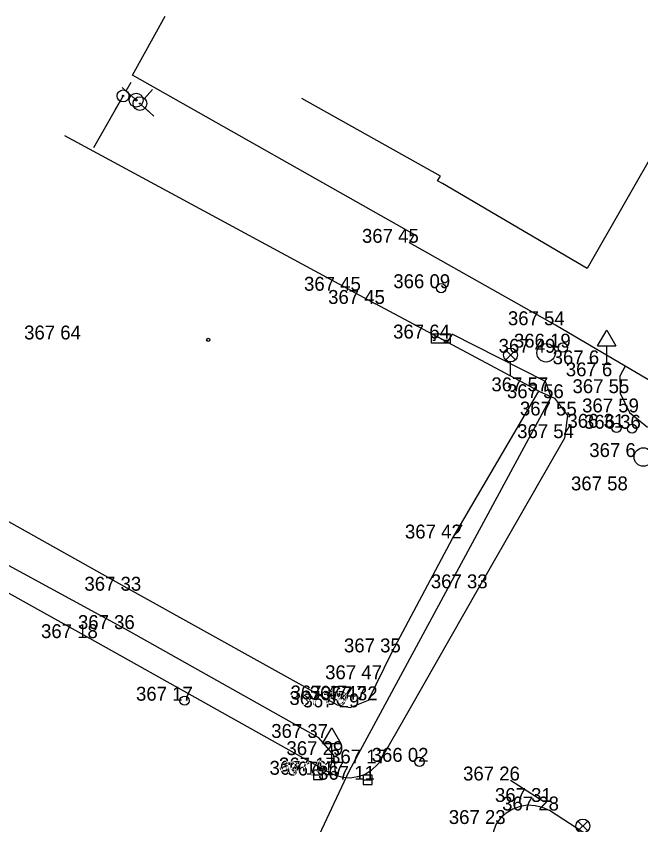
# Model space of a CAD drawing. Extents: x -688316 to -688024, y -973785 to -973591.
# Drawn here: x -688191.59 to -688157.86, y -973639.59 to -973595.92 of the extents above; entities that cross this region are included whole.
import ezdxf

# ---------------------------------------------------------------- set-up
doc = ezdxf.new("R2010")
doc.units = 0
for name, color, linetype in [('Vrstva 10', 7, 'Continuous'), ('Vrstva 11', 7, 'Continuous'), ('Vrstva 17', 7, 'Continuous'), ('Vrstva 1_elektro CEZ', 7, 'Continuous'), ('Vrstva 24', 7, 'Continuous'), ('Vrstva 27', 7, 'Continuous'), ('Vrstva 28_Verejne osvetleni', 7, 'Continuous'), ('Vrstva 3', 7, 'Continuous'), ('Vrstva 33', 7, 'Continuous'), ('Vrstva 34', 7, 'Continuous'), ('Vrstva 5', 7, 'Continuous'), ('Vrstva 50_telekomunikace cetin WMS', 7, 'Continuous'), ('Vrstva 58', 7, 'Continuous'), ('Vrstva 6', 7, 'Continuous'), ('Vrstva 9', 7, 'Continuous')]:
    doc.layers.add(name, color=color, linetype=linetype)

# ---------------------------------------------------------------- blocks, each defined once
blk = doc.blocks.new('DZ')
at = {"layer": 'Vrstva 34'}
for p, q in [((-5, 10), (0, 18.5)), ((0, 18.5), (5, 10)), ((-5, 10), (5, 10)), ((0, 0), (0, 10)), ((-2.49, 0), (2.49, 0))]:
    blk.add_line(p, q, dxfattribs=at)
blk = doc.blocks.new('B_NESP')
at = {"layer": 'Vrstva 58'}
blk.add_circle((0, 0), 0.875, dxfattribs=at)
blk = doc.blocks.new('SAK')
at = {"layer": 'Vrstva 27'}
blk.add_circle((0, 0), 5, dxfattribs=at)
blk = doc.blocks.new('SV')
at = {"layer": 'Vrstva 28_Verejne osvetleni'}
blk.add_circle((0, 0), 2.5, dxfattribs=at)
blk = doc.blocks.new('LAO')
at = {"layer": 'Vrstva 33'}
for p, q in [((-2.65, 14.16), (2.65, 8.85)), ((-2.65, 8.85), (2.65, 14.16)), ((0, 0), (0, 7.75))]:
    blk.add_line(p, q, dxfattribs=at)
blk.add_circle((0, 11.5), 3.75, dxfattribs=at)
blk = doc.blocks.new('PE')
at = {"layer": 'Vrstva 24'}
for p, q in [((-5, 2.5), (5, 2.5)), ((-5, -2.5), (-5, 2.5)), ((-3.11, 1.66), (1.89, -0.84)), ((-3.11, -0.84), (-3.11, 1.66)), ((5, 2.5), (5, -2.5)), ((5, -2.5), (-5, -2.5)), ((-4.21, -0.84), (-3.11, -0.84)), ((1.89, -0.84), (4.34, -0.84))]:
    blk.add_line(p, q, dxfattribs=at)
blk = doc.blocks.new('VP')
at = {"layer": 'Vrstva 27'}
blk.add_line((-2.5, 0), (2.5, 0), dxfattribs=at)
blk.add_lwpolyline([(-2.5, -2.5), (2.5, -2.5), (2.5, 2.5), (-2.5, 2.5)], close=True, dxfattribs=at)
blk = doc.blocks.new('LA')
at = {"layer": 'Vrstva 33'}
for p, q in [((-2.65, 14.15), (2.65, 8.85)), ((-2.65, 8.85), (2.65, 14.15)), ((0, 0), (0, 7.75))]:
    blk.add_line(p, q, dxfattribs=at)
for centre, radius in [((0, 11.5), 3.75), ((0, 0), 1.9), ((0, 0), 0.5)]:
    blk.add_circle(centre, radius, dxfattribs=at)
blk = doc.blocks.new('SOU_20')
at = {"layer": 'Vrstva 11'}
for p, q in [((4.95, 0), (13.28, -0.01)), ((-13.27, 0), (-4.95, -0.02))]:
    blk.add_line(p, q, dxfattribs=at)
for radius in [4.95, 0.584]:
    blk.add_circle((0, -0.01), radius, dxfattribs=at)
blk = doc.blocks.new('SOU_23')
at = {"layer": 'Vrstva 11'}
for p, q in [((4.95, 0), (13.28, 0)), ((-13.27, -0.01), (-4.95, 0))]:
    blk.add_line(p, q, dxfattribs=at)
for radius in [4.95, 0.584]:
    blk.add_circle((0, 0), radius, dxfattribs=at)
blk = doc.blocks.new('HYD_7')
at = {"layer": 'Vrstva 9'}
for p, q in [((0, 13.22), (0.11, 4.84)), ((4.83, 0.01), (13.21, 0.01)), ((-13.17, -0.02), (-4.83, -0.01))]:
    blk.add_line(p, q, dxfattribs=at)
for radius in [4.84, 4.84, 0.334, 0.334]:
    blk.add_circle((0, 0), radius, dxfattribs=at)

msp = doc.modelspace()

# ---------------------------------------------------------------- linework, layer by layer
at = {"layer": 'Vrstva 10'}
for p, q in [((-688161.97, -973618.71), (-688166.62, -973626.82)), ((-688195.18, -973621.46), (-688185.33, -973626.95)), ((-688185.68, -973629.02), (-688196.14, -973623.35)), ((-688171.31, -973630.28), (-688168.03, -973624.13)), ((-688194.8, -973625.52), (-688187.63, -973629.51)), ((-688166.62, -973626.82), (-688170.39, -973633.42)), ((-688185.33, -973626.95), (-688174.26, -973633.12)), ((-688175.24, -973634.9), (-688185.68, -973629.02)), ((-688187.63, -973629.51), (-688174.78, -973636.71)), ((-688174.78, -973636.71), (-688174.33, -973636.93))]:
    msp.add_line(p, q, dxfattribs=at)
for points in [[(-688158.71, -973614.82), (-688158.99, -973615.37), (-688158.98, -973616.01), (-688158.98, -973616.28), (-688158.46, -973617.32), (-688157.5, -973618.12)], [(-688163.36, -973616.18), (-688162.52, -973616.55), (-688161.82, -973617.49), (-688161.97, -973618.71)], [(-688174.26, -973633.12), (-688173.56, -973633.25), (-688172.56, -973632.87), (-688171.31, -973630.28)], [(-688170.39, -973633.42), (-688172.02, -973636.28), (-688172.43, -973636.68), (-688172.78, -973636.89), (-688173.15, -973637.01), (-688173.55, -973637.07), (-688173.95, -973637.04), (-688174.33, -973636.93)], [(-688174.33, -973636.93), (-688174.43, -973635.83), (-688175.24, -973634.9)], [(-688163.16, -973638.65), (-688163.56, -973638.56), (-688163.97, -973638.54), (-688164.38, -973638.61), (-688164.77, -973638.75), (-688165.12, -973638.96), (-688165.43, -973639.24), (-688165.66, -973639.55), (-688165.81, -973639.94), (-688165.88, -973640.34), (-688165.86, -973640.76), (-688165.77, -973641.16), (-688165.61, -973641.54), (-688165.37, -973641.88), (-688165.13, -973642.12)], [(-688154.77, -973644.07), (-688158.8, -973641.42), (-688160.27, -973640.46), (-688162.78, -973638.82), (-688163.16, -973638.65)]]:
    msp.add_lwpolyline(points, dxfattribs=at)
at = {"layer": 'Vrstva 17'}
msp.add_lwpolyline([(-688185.8, -973600.2), (-688185.817, -973600.228), (-688187.413, -973603.038)], dxfattribs=at)
at = {"layer": 'Vrstva 1_elektro CEZ'}
msp.add_lwpolyline([(-688190.282, -973658.121), (-688190.282, -973658.255), (-688190.094, -973658.256), (-688190.531, -973658.736), (-688188.15, -973660.224), (-688187.569, -973659.901), (-688184.139, -973653.841), (-688183.153, -973652.126), (-688176.422, -973642.693), (-688173.607, -973636.693), (-688162.702, -973616.499), (-688163.01, -973615.648), (-688168.054, -973613.093), (-688168.316, -973613.534), (-688168.345, -973613.555), (-688168.465, -973613.555), (-688168.465, -973613.42)], dxfattribs=at)
at = {"layer": 'Vrstva 5'}
for p, q in [((-688154.72, -973598.97), (-688160.75, -973609.55)), ((-688168.68, -973604.57), (-688176.17, -973600.36)), ((-688173.48, -973610.75), (-688188.96, -973602.39)), ((-688168.83, -973604.81), (-688168.68, -973604.57)), ((-688168.57, -973604.96), (-688168.83, -973604.81)), ((-688160.75, -973609.55), (-688168.57, -973604.96)), ((-688163.36, -973616.18), (-688172.18, -973611.46)), ((-688168.03, -973624.13), (-688163.36, -973616.18))]:
    msp.add_line(p, q, dxfattribs=at)
for points in [[(-688162.47, -973612.61), (-688170.35, -973608.16), (-688170.09, -973607.71), (-688185.31, -973599.11), (-688183.54, -973595.92)], [(-688154.93, -973617.04), (-688155.61, -973616.64), (-688158.71, -973614.82), (-688162.47, -973612.61)]]:
    msp.add_lwpolyline(points, dxfattribs=at)
at = {"layer": 'Vrstva 50_telekomunikace cetin WMS'}
for points in [[(-688167.65, -973623.61), (-688167.73, -973623.73)], [(-688167.65, -973623.61), (-688167.51, -973623.4)]]:
    msp.add_lwpolyline(points, dxfattribs=at)
at = {"layer": 'Vrstva 6'}
msp.add_line((-688173.48, -973610.75), (-688172.18, -973611.46), dxfattribs=at)
at = {"layer": 'Vrstva 9'}
msp.add_line((-688163.1, -973638.36), (-688164.89, -973637.2), dxfattribs=at)

# ---------------------------------------------------------------- block references
at = {"layer": 'Vrstva 11'}
for name, p, xscale, yscale, rotation in [('SOU_20', (-688185.817, -973600.228), 0.06499977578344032, 0.06499977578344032, 60.388306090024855), ('SOU_23', (-688185.115, -973600.454), 0.07619954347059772, 0.07619954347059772, 137.8620466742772)]:
    msp.add_blockref(name, p, dxfattribs=dict(at, xscale=xscale, yscale=yscale, rotation=rotation))
at = {"layer": 'Vrstva 24', "xscale": 0.1, "yscale": 0.10000000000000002}
msp.add_blockref('PE', (-688168.66, -973613.33), dxfattribs=at)
at = {"layer": 'Vrstva 27', "xscale": 0.1, "yscale": 0.10000000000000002}
for name, p in [('SAK', (-688162.97, -973614.1)), ('SAK', (-688157.72, -973619.73)), ('VP', (-688175.29, -973636.89)), ('VP', (-688172.61, -973637.16))]:
    msp.add_blockref(name, p, dxfattribs=at)
at = {"layer": 'Vrstva 28_Verejne osvetleni', "xscale": 0.1, "yscale": 0.10000000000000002}
for p in [(-688168.64, -973610.61), (-688162.07, -973613.82), (-688159.17, -973618.15), (-688158.33, -973618.2), (-688182.5, -973632.89), (-688169.81, -973636.19)]:
    msp.add_blockref('SV', p, dxfattribs=at)
at = {"layer": 'Vrstva 33', "xscale": 0.1, "yscale": 0.10000000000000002}
for name, p in [('LAO', (-688164.89, -973615.37)), ('LA', (-688160.99, -973640.81))]:
    msp.add_blockref(name, p, dxfattribs=at)
at = {"layer": 'Vrstva 34', "xscale": 0.1, "yscale": 0.10000000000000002}
for p in [(-688159.7, -973614.72), (-688159.7, -973614.72), (-688159.7, -973614.72), (-688159.7, -973614.72), (-688174.55, -973636.2), (-688174.55, -973636.2), (-688174.55, -973636.2), (-688174.55, -973636.2)]:
    msp.add_blockref('DZ', p, dxfattribs=at)
at = {"layer": 'Vrstva 58', "xscale": 0.1, "yscale": 0.10000000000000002}
msp.add_blockref('B_NESP', (-688181.22, -973613.4), dxfattribs=at)
msp.add_blockref('B_NESP', (-688181.22, -973613.4), dxfattribs=at)
msp.add_blockref('B_NESP', (-688181.22, -973613.4), dxfattribs=at)
msp.add_blockref('B_NESP', (-688181.22, -973613.4), dxfattribs=at)
at = {"layer": 'Vrstva 9', "xscale": 0.07659945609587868, "yscale": 0.07659945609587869, "rotation": -42.13786535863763}
msp.add_blockref('HYD_7', (-688184.91, -973600.639), dxfattribs=at)

# ---------------------------------------------------------------- texts
at = {"layer": 'Vrstva 3'}
for s, p in [('367 45 ', (-688172.916, -973608.16)), ('367 45 ', (-688172.916, -973608.16)), ('367 45 ', (-688172.916, -973608.16)), ('367 45 ', (-688172.916, -973608.16)), ('367 45 ', (-688172.916, -973608.16)), ('367 45 ', (-688172.916, -973608.16)), ('367 45 ', (-688172.916, -973608.16)), ('367 45 ', (-688176.046, -973610.75)), ('367 45 ', (-688176.046, -973610.75)), ('367 45 ', (-688176.046, -973610.75)), ('367 45 ', (-688176.046, -973610.75)), ('367 45 ', (-688176.046, -973610.75)), ('367 45 ', (-688176.046, -973610.75)), ('367 45 ', (-688176.046, -973610.75)), ('366 09 ', (-688171.223, -973610.61)), ('366 09 ', (-688171.223, -973610.61)), ('366 09 ', (-688171.223, -973610.61)), ('366 09 ', (-688171.223, -973610.61)), ('366 09 ', (-688171.223, -973610.61)), ('366 09 ', (-688171.223, -973610.61)), ('366 09 ', (-688171.223, -973610.61)), ('367 45 ', (-688174.746, -973611.46)), ('367 45 ', (-688174.746, -973611.46)), ('367 45 ', (-688174.746, -973611.46)), ('367 45 ', (-688174.746, -973611.46)), ('367 45 ', (-688174.746, -973611.46)), ('367 45 ', (-688174.746, -973611.46)), ('367 45 ', (-688174.746, -973611.46)), ('367 54 ', (-688165.036, -973612.61)), ('367 54 ', (-688165.036, -973612.61)), ('367 54 ', (-688165.036, -973612.61)), ('367 54 ', (-688165.036, -973612.61)), ('367 54 ', (-688165.036, -973612.61)), ('367 54 ', (-688165.036, -973612.61)), ('367 54 ', (-688165.036, -973612.61)), ('367 64 ', (-688191.165, -973613.38)), ('367 64 ', (-688191.165, -973613.38)), ('367 64 ', (-688191.165, -973613.38)), ('367 64 ', (-688191.165, -973613.38)), ('367 64 ', (-688191.165, -973613.38)), ('367 64 ', (-688191.165, -973613.38)), ('367 64 ', (-688191.165, -973613.38)), ('367 64 ', (-688171.235, -973613.33)), ('367 64 ', (-688171.235, -973613.33)), ('367 64 ', (-688171.235, -973613.33)), ('367 64 ', (-688171.235, -973613.33)), ('367 64 ', (-688171.235, -973613.33)), ('367 64 ', (-688171.235, -973613.33)), ('367 64 ', (-688171.235, -973613.33)), ('366 19 ', (-688164.709, -973613.82)), ('366 19 ', (-688164.709, -973613.82)), ('366 19 ', (-688164.709, -973613.82)), ('366 19 ', (-688164.709, -973613.82)), ('366 19 ', (-688164.709, -973613.82)), ('366 19 ', (-688164.709, -973613.82)), ('366 19 ', (-688164.709, -973613.82)), ('367 49 ', (-688165.536, -973614.1)), ('367 49 ', (-688165.536, -973614.1)), ('367 49 ', (-688165.536, -973614.1)), ('367 49 ', (-688165.536, -973614.1)), ('367 49 ', (-688165.536, -973614.1)), ('367 49 ', (-688165.536, -973614.1)), ('367 49 ', (-688165.536, -973614.1)), ('367 6  ', (-688162.617, -973614.72)), ('367 6  ', (-688162.617, -973614.72)), ('367 6  ', (-688162.617, -973614.72)), ('367 6  ', (-688162.617, -973614.72)), ('367 6  ', (-688162.617, -973614.72)), ('367 6  ', (-688162.617, -973614.72)), ('367 6  ', (-688162.617, -973614.72)), ('367 6  ', (-688161.907, -973615.37)), ('367 6  ', (-688161.907, -973615.37)), ('367 6  ', (-688161.907, -973615.37)), ('367 6  ', (-688161.907, -973615.37)), ('367 6  ', (-688161.907, -973615.37)), ('367 6  ', (-688161.907, -973615.37)), ('367 6  ', (-688161.907, -973615.37)), ('367 57 ', (-688165.926, -973616.18)), ('367 57 ', (-688165.926, -973616.18)), ('367 57 ', (-688165.926, -973616.18)), ('367 57 ', (-688165.926, -973616.18)), ('367 57 ', (-688165.926, -973616.18)), ('367 57 ', (-688165.926, -973616.18)), ('367 57 ', (-688165.926, -973616.18)), ('367 56 ', (-688165.086, -973616.55)), ('367 56 ', (-688165.086, -973616.55)), ('367 56 ', (-688165.086, -973616.55)), ('367 56 ', (-688165.086, -973616.55)), ('367 56 ', (-688165.086, -973616.55)), ('367 56 ', (-688165.086, -973616.55)), ('367 56 ', (-688165.086, -973616.55)), ('367 55 ', (-688161.546, -973616.28)), ('367 55 ', (-688161.546, -973616.28)), ('367 55 ', (-688161.546, -973616.28)), ('367 55 ', (-688161.546, -973616.28)), ('367 55 ', (-688161.546, -973616.28)), ('367 55 ', (-688161.546, -973616.28)), ('367 55 ', (-688161.546, -973616.28)), ('367 55 ', (-688164.386, -973617.49)), ('367 55 ', (-688164.386, -973617.49)), ('367 55 ', (-688164.386, -973617.49)), ('367 55 ', (-688164.386, -973617.49)), ('367 55 ', (-688164.386, -973617.49)), ('367 55 ', (-688164.386, -973617.49)), ('367 55 ', (-688164.386, -973617.49)), ('367 59 ', (-688161.026, -973617.32)), ('367 59 ', (-688161.026, -973617.32)), ('367 59 ', (-688161.026, -973617.32)), ('367 59 ', (-688161.026, -973617.32)), ('367 59 ', (-688161.026, -973617.32)), ('367 59 ', (-688161.026, -973617.32)), ('367 59 ', (-688161.026, -973617.32)), ('366 31 ', (-688161.821, -973618.15)), ('366 31 ', (-688161.821, -973618.15)), ('366 31 ', (-688161.821, -973618.15)), ('366 31 ', (-688161.821, -973618.15)), ('366 31 ', (-688161.821, -973618.15)), ('366 31 ', (-688161.821, -973618.15)), ('366 31 ', (-688161.821, -973618.15)), ('366 36 ', (-688160.925, -973618.2)), ('366 36 ', (-688160.925, -973618.2)), ('366 36 ', (-688160.925, -973618.2)), ('366 36 ', (-688160.925, -973618.2)), ('366 36 ', (-688160.925, -973618.2)), ('366 36 ', (-688160.925, -973618.2)), ('366 36 ', (-688160.925, -973618.2)), ('367 54 ', (-688164.536, -973618.71)), ('367 54 ', (-688164.536, -973618.71)), ('367 54 ', (-688164.536, -973618.71)), ('367 54 ', (-688164.536, -973618.71)), ('367 54 ', (-688164.536, -973618.71)), ('367 54 ', (-688164.536, -973618.71)), ('367 54 ', (-688164.536, -973618.71)), ('367 6  ', (-688160.637, -973619.73)), ('367 6  ', (-688160.637, -973619.73)), ('367 6  ', (-688160.637, -973619.73)), ('367 6  ', (-688160.637, -973619.73)), ('367 6  ', (-688160.637, -973619.73)), ('367 6  ', (-688160.637, -973619.73)), ('367 6  ', (-688160.637, -973619.73)), ('367 58 ', (-688161.626, -973621.53)), ('367 58 ', (-688161.626, -973621.53)), ('367 58 ', (-688161.626, -973621.53)), ('367 58 ', (-688161.626, -973621.53)), ('367 58 ', (-688161.626, -973621.53)), ('367 58 ', (-688161.626, -973621.53)), ('367 58 ', (-688161.626, -973621.53)), ('367 42 ', (-688170.596, -973624.13)), ('367 42 ', (-688170.596, -973624.13)), ('367 42 ', (-688170.596, -973624.13)), ('367 42 ', (-688170.596, -973624.13)), ('367 42 ', (-688170.596, -973624.13)), ('367 42 ', (-688170.596, -973624.13)), ('367 42 ', (-688170.596, -973624.13)), ('367 33 ', (-688187.908, -973626.95)), ('367 33 ', (-688187.908, -973626.95)), ('367 33 ', (-688187.908, -973626.95)), ('367 33 ', (-688187.908, -973626.95)), ('367 33 ', (-688187.908, -973626.95)), ('367 33 ', (-688187.908, -973626.95)), ('367 33 ', (-688187.908, -973626.95)), ('367 33 ', (-688169.198, -973626.82)), ('367 33 ', (-688169.198, -973626.82)), ('367 33 ', (-688169.198, -973626.82)), ('367 33 ', (-688169.198, -973626.82)), ('367 33 ', (-688169.198, -973626.82)), ('367 33 ', (-688169.198, -973626.82)), ('367 33 ', (-688169.198, -973626.82)), ('367 36 ', (-688188.258, -973629.02)), ('367 36 ', (-688188.258, -973629.02)), ('367 36 ', (-688188.258, -973629.02)), ('367 36 ', (-688188.258, -973629.02)), ('367 36 ', (-688188.258, -973629.02)), ('367 36 ', (-688188.258, -973629.02)), ('367 36 ', (-688188.258, -973629.02)), ('367 18 ', (-688190.251, -973629.51)), ('367 18 ', (-688190.251, -973629.51)), ('367 18 ', (-688190.251, -973629.51)), ('367 18 ', (-688190.251, -973629.51)), ('367 18 ', (-688190.251, -973629.51)), ('367 18 ', (-688190.251, -973629.51)), ('367 18 ', (-688190.251, -973629.51)), ('367 35 ', (-688173.888, -973630.28)), ('367 35 ', (-688173.888, -973630.28)), ('367 35 ', (-688173.888, -973630.28)), ('367 35 ', (-688173.888, -973630.28)), ('367 35 ', (-688173.888, -973630.28)), ('367 35 ', (-688173.888, -973630.28)), ('367 35 ', (-688173.888, -973630.28)), ('367 47 ', (-688174.906, -973631.73)), ('367 47 ', (-688174.906, -973631.73)), ('367 47 ', (-688174.906, -973631.73)), ('367 47 ', (-688174.906, -973631.73)), ('367 47 ', (-688174.906, -973631.73)), ('367 47 ', (-688174.906, -973631.73)), ('367 47 ', (-688174.906, -973631.73)), ('367 47 ', (-688176.776, -973632.82)), ('367 47 ', (-688176.776, -973632.82)), ('367 47 ', (-688176.776, -973632.82)), ('367 47 ', (-688176.776, -973632.82)), ('367 47 ', (-688176.776, -973632.82)), ('367 47 ', (-688176.776, -973632.82)), ('367 47 ', (-688176.776, -973632.82)), ('367 47 ', (-688175.736, -973632.84)), ('367 47 ', (-688175.736, -973632.84)), ('367 47 ', (-688175.736, -973632.84)), ('367 47 ', (-688175.736, -973632.84)), ('367 47 ', (-688175.736, -973632.84)), ('367 47 ', (-688175.736, -973632.84)), ('367 47 ', (-688175.736, -973632.84)), ('367 17 ', (-688185.121, -973632.89)), ('367 17 ', (-688185.121, -973632.89)), ('367 17 ', (-688185.121, -973632.89)), ('367 17 ', (-688185.121, -973632.89)), ('367 17 ', (-688185.121, -973632.89)), ('367 17 ', (-688185.121, -973632.89)), ('367 17 ', (-688185.121, -973632.89)), ('367 38 ', (-688176.838, -973633.12)), ('367 38 ', (-688176.838, -973633.12)), ('367 38 ', (-688176.838, -973633.12)), ('367 38 ', (-688176.838, -973633.12)), ('367 38 ', (-688176.838, -973633.12)), ('367 38 ', (-688176.838, -973633.12)), ('367 38 ', (-688176.838, -973633.12)), ('367 29 ', (-688176.126, -973633.25)), ('367 29 ', (-688176.126, -973633.25)), ('367 29 ', (-688176.126, -973633.25)), ('367 29 ', (-688176.126, -973633.25)), ('367 29 ', (-688176.126, -973633.25)), ('367 29 ', (-688176.126, -973633.25)), ('367 29 ', (-688176.126, -973633.25)), ('367 32 ', (-688175.138, -973632.87)), ('367 32 ', (-688175.138, -973632.87)), ('367 32 ', (-688175.138, -973632.87)), ('367 32 ', (-688175.138, -973632.87)), ('367 32 ', (-688175.138, -973632.87)), ('367 32 ', (-688175.138, -973632.87)), ('367 32 ', (-688175.138, -973632.87)), ('367 37 ', (-688177.818, -973634.9)), ('367 37 ', (-688177.818, -973634.9)), ('367 37 ', (-688177.818, -973634.9)), ('367 37 ', (-688177.818, -973634.9)), ('367 37 ', (-688177.818, -973634.9)), ('367 37 ', (-688177.818, -973634.9)), ('367 37 ', (-688177.818, -973634.9)), ('367 29 ', (-688176.996, -973635.83)), ('367 29 ', (-688176.996, -973635.83)), ('367 29 ', (-688176.996, -973635.83)), ('367 29 ', (-688176.996, -973635.83)), ('367 29 ', (-688176.996, -973635.83)), ('367 29 ', (-688176.996, -973635.83)), ('367 29 ', (-688176.996, -973635.83)), ('367 17 ', (-688174.641, -973636.28)), ('367 17 ', (-688174.641, -973636.28)), ('367 17 ', (-688174.641, -973636.28)), ('367 17 ', (-688174.641, -973636.28)), ('367 17 ', (-688174.641, -973636.28)), ('367 17 ', (-688174.641, -973636.28)), ('367 17 ', (-688174.641, -973636.28)), ('366 02 ', (-688172.393, -973636.19)), ('366 02 ', (-688172.393, -973636.19)), ('366 02 ', (-688172.393, -973636.19)), ('366 02 ', (-688172.393, -973636.19)), ('366 02 ', (-688172.393, -973636.19)), ('366 02 ', (-688172.393, -973636.19)), ('366 02 ', (-688172.393, -973636.19)), ('367 17 ', (-688177.401, -973636.71)), ('367 17 ', (-688177.401, -973636.71)), ('367 17 ', (-688177.401, -973636.71)), ('367 17 ', (-688177.401, -973636.71)), ('367 17 ', (-688177.401, -973636.71)), ('367 17 ', (-688177.401, -973636.71)), ('367 17 ', (-688177.401, -973636.71)), ('367 16 ', (-688177.911, -973636.89)), ('367 16 ', (-688177.911, -973636.89)), ('367 16 ', (-688177.911, -973636.89)), ('367 16 ', (-688177.911, -973636.89)), ('367 16 ', (-688177.911, -973636.89)), ('367 16 ', (-688177.911, -973636.89)), ('367 16 ', (-688177.911, -973636.89)), ('367 17 ', (-688176.951, -973636.93)), ('367 17 ', (-688176.951, -973636.93)), ('367 17 ', (-688176.951, -973636.93)), ('367 17 ', (-688176.951, -973636.93)), ('367 17 ', (-688176.951, -973636.93)), ('367 17 ', (-688176.951, -973636.93)), ('367 17 ', (-688176.951, -973636.93)), ('367 11 ', (-688175.287, -973637.16)), ('367 11 ', (-688175.287, -973637.16)), ('367 11 ', (-688175.287, -973637.16)), ('367 11 ', (-688175.287, -973637.16)), ('367 11 ', (-688175.287, -973637.16)), ('367 11 ', (-688175.287, -973637.16)), ('367 11 ', (-688175.287, -973637.16)), ('367 26 ', (-688167.456, -973637.2)), ('367 26 ', (-688167.456, -973637.2)), ('367 26 ', (-688167.456, -973637.2)), ('367 26 ', (-688167.456, -973637.2)), ('367 26 ', (-688167.456, -973637.2)), ('367 26 ', (-688167.456, -973637.2)), ('367 26 ', (-688167.456, -973637.2)), ('367 31 ', (-688165.733, -973638.36)), ('367 31 ', (-688165.733, -973638.36)), ('367 31 ', (-688165.733, -973638.36)), ('367 31 ', (-688165.733, -973638.36)), ('367 31 ', (-688165.733, -973638.36)), ('367 31 ', (-688165.733, -973638.36)), ('367 31 ', (-688165.733, -973638.36)), ('367 28 ', (-688165.346, -973638.82)), ('367 28 ', (-688165.346, -973638.82)), ('367 28 ', (-688165.346, -973638.82)), ('367 28 ', (-688165.346, -973638.82)), ('367 28 ', (-688165.346, -973638.82)), ('367 28 ', (-688165.346, -973638.82)), ('367 28 ', (-688165.346, -973638.82)), ('367 23 ', (-688168.226, -973639.55)), ('367 23 ', (-688168.226, -973639.55)), ('367 23 ', (-688168.226, -973639.55)), ('367 23 ', (-688168.226, -973639.55)), ('367 23 ', (-688168.226, -973639.55)), ('367 23 ', (-688168.226, -973639.55)), ('367 23 ', (-688168.226, -973639.55))]:
    msp.add_text(s, height=0.75, dxfattribs=at).set_placement(p)

doc.saveas('drawing.dxf')
